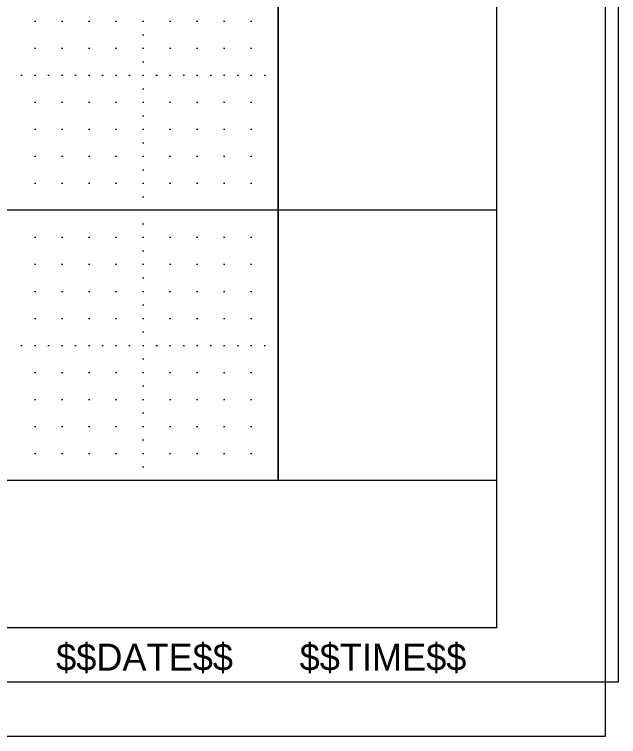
# Model space of a CAD drawing. Extents: x -3.6 to 32.1, y -0.4 to 20.9.
# Drawn here: x 29.832 to 32.067, y -0.403 to 2.27 of the extents above; entities that cross this region are included whole.
import ezdxf

# ---------------------------------------------------------------- set-up
doc = ezdxf.new("R2010")
doc.units = 0
for name, color, linetype in [('Level 1', 7, 'Continuous'), ('Level 37', 7, 'Continuous'), ('Level 4', 7, 'Continuous'), ('Level 48', 7, 'Continuous'), ('Level 5', 7, 'Continuous'), ('Level 63', 7, 'Continuous'), ('Level 63 Full', 7, 'Continuous')]:
    doc.layers.add(name, color=color, linetype=linetype)

msp = doc.modelspace()

# ---------------------------------------------------------------- linework, layer by layer
at = {"layer": 'Level 1'}
for q in [(31.617, 20.545), (-0.001, -0.001)]:
    msp.add_line((31.617, -0.001), q, dxfattribs=at)
at = {"layer": 'Level 37'}
msp.add_lwpolyline([(0.808, 9.545), (30.808, 9.545), (30.808, 0.545), (0.808, 0.545)], close=True, dxfattribs=at)
at = {"layer": 'Level 4'}
for p, q in [((30.808, 0.545), (30.808, 9.545)), ((31.617, 1.545), (-0.001, 1.545)), ((31.617, 0.545), (-0.001, 0.545))]:
    msp.add_line(p, q, dxfattribs=at)
at = {"layer": 'Level 5'}
for p, q in [((29.9055, 2.245), (29.9105, 2.245)), ((30.0055, 2.245), (30.0105, 2.245)), ((30.1055, 2.245), (30.1105, 2.245)), ((30.2055, 2.245), (30.2105, 2.245)), ((30.3055, 2.245), (30.3105, 2.245)), ((30.4055, 2.245), (30.4105, 2.245)), ((30.5055, 2.245), (30.5105, 2.245)), ((30.6055, 2.245), (30.6105, 2.245)), ((30.7055, 2.245), (30.7105, 2.245)), ((30.3055, 2.195), (30.3105, 2.195)), ((29.9055, 2.145), (29.9105, 2.145)), ((30.0055, 2.145), (30.0105, 2.145)), ((30.1055, 2.145), (30.1105, 2.145)), ((30.2055, 2.145), (30.2105, 2.145)), ((30.3055, 2.145), (30.3105, 2.145)), ((30.4055, 2.145), (30.4105, 2.145)), ((30.5055, 2.145), (30.5105, 2.145)), ((30.6055, 2.145), (30.6105, 2.145)), ((30.7055, 2.145), (30.7105, 2.145)), ((30.3055, 2.095), (30.3105, 2.095)), ((29.8555, 2.045), (29.8605, 2.045)), ((29.9055, 2.045), (29.9105, 2.045)), ((29.9555, 2.045), (29.9605, 2.045)), ((30.0055, 2.045), (30.0105, 2.045)), ((30.0555, 2.045), (30.0605, 2.045)), ((30.1055, 2.045), (30.1105, 2.045)), ((30.1555, 2.045), (30.1605, 2.045)), ((30.2055, 2.045), (30.2105, 2.045)), ((30.2555, 2.045), (30.2605, 2.045)), ((30.3055, 2.045), (30.3105, 2.045)), ((30.3555, 2.045), (30.3605, 2.045)), ((30.4055, 2.045), (30.4105, 2.045)), ((30.4555, 2.045), (30.4605, 2.045)), ((30.5055, 2.045), (30.5105, 2.045)), ((30.5555, 2.045), (30.5605, 2.045)), ((30.6055, 2.045), (30.6105, 2.045)), ((30.6555, 2.045), (30.6605, 2.045)), ((30.7055, 2.045), (30.7105, 2.045)), ((30.7555, 2.045), (30.7605, 2.045)), ((30.3055, 1.995), (30.3105, 1.995)), ((29.9055, 1.945), (29.9105, 1.945)), ((30.0055, 1.945), (30.0105, 1.945)), ((30.1055, 1.945), (30.1105, 1.945)), ((30.2055, 1.945), (30.2105, 1.945)), ((30.3055, 1.945), (30.3105, 1.945)), ((30.4055, 1.945), (30.4105, 1.945)), ((30.5055, 1.945), (30.5105, 1.945)), ((30.6055, 1.945), (30.6105, 1.945)), ((30.7055, 1.945), (30.7105, 1.945)), ((30.3055, 1.895), (30.3105, 1.895)), ((29.9055, 1.845), (29.9105, 1.845)), ((30.0055, 1.845), (30.0105, 1.845)), ((30.1055, 1.845), (30.1105, 1.845)), ((30.2055, 1.845), (30.2105, 1.845)), ((30.3055, 1.845), (30.3105, 1.845)), ((30.4055, 1.845), (30.4105, 1.845)), ((30.5055, 1.845), (30.5105, 1.845)), ((30.6055, 1.845), (30.6105, 1.845)), ((30.7055, 1.845), (30.7105, 1.845)), ((30.3055, 1.795), (30.3105, 1.795)), ((29.9055, 1.745), (29.9105, 1.745)), ((30.0055, 1.745), (30.0105, 1.745)), ((30.1055, 1.745), (30.1105, 1.745)), ((30.2055, 1.745), (30.2105, 1.745)), ((30.3055, 1.745), (30.3105, 1.745)), ((30.4055, 1.745), (30.4105, 1.745)), ((30.5055, 1.745), (30.5105, 1.745)), ((30.6055, 1.745), (30.6105, 1.745)), ((30.7055, 1.745), (30.7105, 1.745)), ((30.3055, 1.695), (30.3105, 1.695)), ((29.9055, 1.645), (29.9105, 1.645)), ((30.0055, 1.645), (30.0105, 1.645)), ((30.1055, 1.645), (30.1105, 1.645)), ((30.2055, 1.645), (30.2105, 1.645)), ((30.3055, 1.645), (30.3105, 1.645)), ((30.4055, 1.645), (30.4105, 1.645)), ((30.5055, 1.645), (30.5105, 1.645)), ((30.6055, 1.645), (30.6105, 1.645)), ((30.7055, 1.645), (30.7105, 1.645)), ((30.3055, 1.595), (30.3105, 1.595)), ((30.3055, 1.495), (30.3105, 1.495)), ((29.9055, 1.445), (29.9105, 1.445)), ((30.0055, 1.445), (30.0105, 1.445)), ((30.1055, 1.445), (30.1105, 1.445)), ((30.2055, 1.445), (30.2105, 1.445)), ((30.3055, 1.445), (30.3105, 1.445)), ((30.4055, 1.445), (30.4105, 1.445)), ((30.5055, 1.445), (30.5105, 1.445)), ((30.6055, 1.445), (30.6105, 1.445)), ((30.7055, 1.445), (30.7105, 1.445)), ((30.3055, 1.395), (30.3105, 1.395)), ((29.9055, 1.345), (29.9105, 1.345)), ((30.0055, 1.345), (30.0105, 1.345)), ((30.1055, 1.345), (30.1105, 1.345)), ((30.2055, 1.345), (30.2105, 1.345)), ((30.3055, 1.345), (30.3105, 1.345)), ((30.4055, 1.345), (30.4105, 1.345)), ((30.5055, 1.345), (30.5105, 1.345)), ((30.6055, 1.345), (30.6105, 1.345)), ((30.7055, 1.345), (30.7105, 1.345)), ((30.3055, 1.295), (30.3105, 1.295)), ((29.9055, 1.245), (29.9105, 1.245)), ((30.0055, 1.245), (30.0105, 1.245)), ((30.1055, 1.245), (30.1105, 1.245)), ((30.2055, 1.245), (30.2105, 1.245)), ((30.3055, 1.245), (30.3105, 1.245)), ((30.4055, 1.245), (30.4105, 1.245)), ((30.5055, 1.245), (30.5105, 1.245)), ((30.6055, 1.245), (30.6105, 1.245)), ((30.7055, 1.245), (30.7105, 1.245)), ((30.3055, 1.195), (30.3105, 1.195)), ((29.9055, 1.145), (29.9105, 1.145)), ((30.0055, 1.145), (30.0105, 1.145)), ((30.1055, 1.145), (30.1105, 1.145)), ((30.2055, 1.145), (30.2105, 1.145)), ((30.3055, 1.145), (30.3105, 1.145)), ((30.4055, 1.145), (30.4105, 1.145)), ((30.5055, 1.145), (30.5105, 1.145)), ((30.6055, 1.145), (30.6105, 1.145)), ((30.7055, 1.145), (30.7105, 1.145)), ((30.3055, 1.095), (30.3105, 1.095)), ((29.8555, 1.045), (29.8605, 1.045)), ((29.9055, 1.045), (29.9105, 1.045)), ((29.9555, 1.045), (29.9605, 1.045)), ((30.0055, 1.045), (30.0105, 1.045)), ((30.0555, 1.045), (30.0605, 1.045)), ((30.1055, 1.045), (30.1105, 1.045)), ((30.1555, 1.045), (30.1605, 1.045)), ((30.2055, 1.045), (30.2105, 1.045)), ((30.2555, 1.045), (30.2605, 1.045)), ((30.3055, 1.045), (30.3105, 1.045)), ((30.3555, 1.045), (30.3605, 1.045)), ((30.4055, 1.045), (30.4105, 1.045)), ((30.4555, 1.045), (30.4605, 1.045)), ((30.5055, 1.045), (30.5105, 1.045)), ((30.5555, 1.045), (30.5605, 1.045)), ((30.6055, 1.045), (30.6105, 1.045)), ((30.6555, 1.045), (30.6605, 1.045)), ((30.7055, 1.045), (30.7105, 1.045)), ((30.7555, 1.045), (30.7605, 1.045)), ((30.3055, 0.995), (30.3105, 0.995)), ((29.9055, 0.945), (29.9105, 0.945)), ((30.0055, 0.945), (30.0105, 0.945)), ((30.1055, 0.945), (30.1105, 0.945)), ((30.2055, 0.945), (30.2105, 0.945)), ((30.3055, 0.945), (30.3105, 0.945)), ((30.4055, 0.945), (30.4105, 0.945)), ((30.5055, 0.945), (30.5105, 0.945)), ((30.6055, 0.945), (30.6105, 0.945)), ((30.7055, 0.945), (30.7105, 0.945)), ((30.3055, 0.895), (30.3105, 0.895)), ((29.9055, 0.845), (29.9105, 0.845)), ((30.0055, 0.845), (30.0105, 0.845)), ((30.1055, 0.845), (30.1105, 0.845)), ((30.2055, 0.845), (30.2105, 0.845)), ((30.3055, 0.845), (30.3105, 0.845)), ((30.4055, 0.845), (30.4105, 0.845)), ((30.5055, 0.845), (30.5105, 0.845)), ((30.6055, 0.845), (30.6105, 0.845)), ((30.7055, 0.845), (30.7105, 0.845)), ((30.3055, 0.795), (30.3105, 0.795)), ((29.9055, 0.745), (29.9105, 0.745)), ((30.0055, 0.745), (30.0105, 0.745)), ((30.1055, 0.745), (30.1105, 0.745)), ((30.2055, 0.745), (30.2105, 0.745)), ((30.3055, 0.745), (30.3105, 0.745)), ((30.4055, 0.745), (30.4105, 0.745)), ((30.5055, 0.745), (30.5105, 0.745)), ((30.6055, 0.745), (30.6105, 0.745)), ((30.7055, 0.745), (30.7105, 0.745)), ((30.3055, 0.695), (30.3105, 0.695)), ((29.9055, 0.645), (29.9105, 0.645)), ((30.0055, 0.645), (30.0105, 0.645)), ((30.1055, 0.645), (30.1105, 0.645)), ((30.2055, 0.645), (30.2105, 0.645)), ((30.3055, 0.645), (30.3105, 0.645)), ((30.4055, 0.645), (30.4105, 0.645)), ((30.5055, 0.645), (30.5105, 0.645)), ((30.6055, 0.645), (30.6105, 0.645)), ((30.7055, 0.645), (30.7105, 0.645)), ((30.3055, 0.595), (30.3105, 0.595))]:
    msp.add_line(p, q, dxfattribs=at)
at = {"layer": 'Level 63'}
msp.add_lwpolyline([(-1.263, -0.2005), (32.067, -0.2005), (32.067, 20.7465), (-1.263, 20.7465)], close=True, dxfattribs=at)
at = {"layer": 'Level 63 Full'}
msp.add_lwpolyline([(32.017, -0.403), (-3.583, -0.403), (-3.583, 20.947), (32.017, 20.947)], close=True, dxfattribs=at)

# ---------------------------------------------------------------- texts
at = {"layer": 'Level 48'}
for s, p in [('$$DATE$$', (29.986, -0.159)), ('$$TIME$$', (30.887, -0.159))]:
    msp.add_text(s, height=0.1, dxfattribs=at).set_placement(p)

doc.saveas('drawing.dxf')
